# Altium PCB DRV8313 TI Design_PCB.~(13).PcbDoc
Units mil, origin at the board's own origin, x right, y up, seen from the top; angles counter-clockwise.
Board outline 4950 x 3450 mil, 2 copper layers (Top Layer, Bottom Layer), stack 62 mil thick; 47 components, 32 nets, 131 pads, 12 vias.
Unrouted connection lines stored in the file: 48.
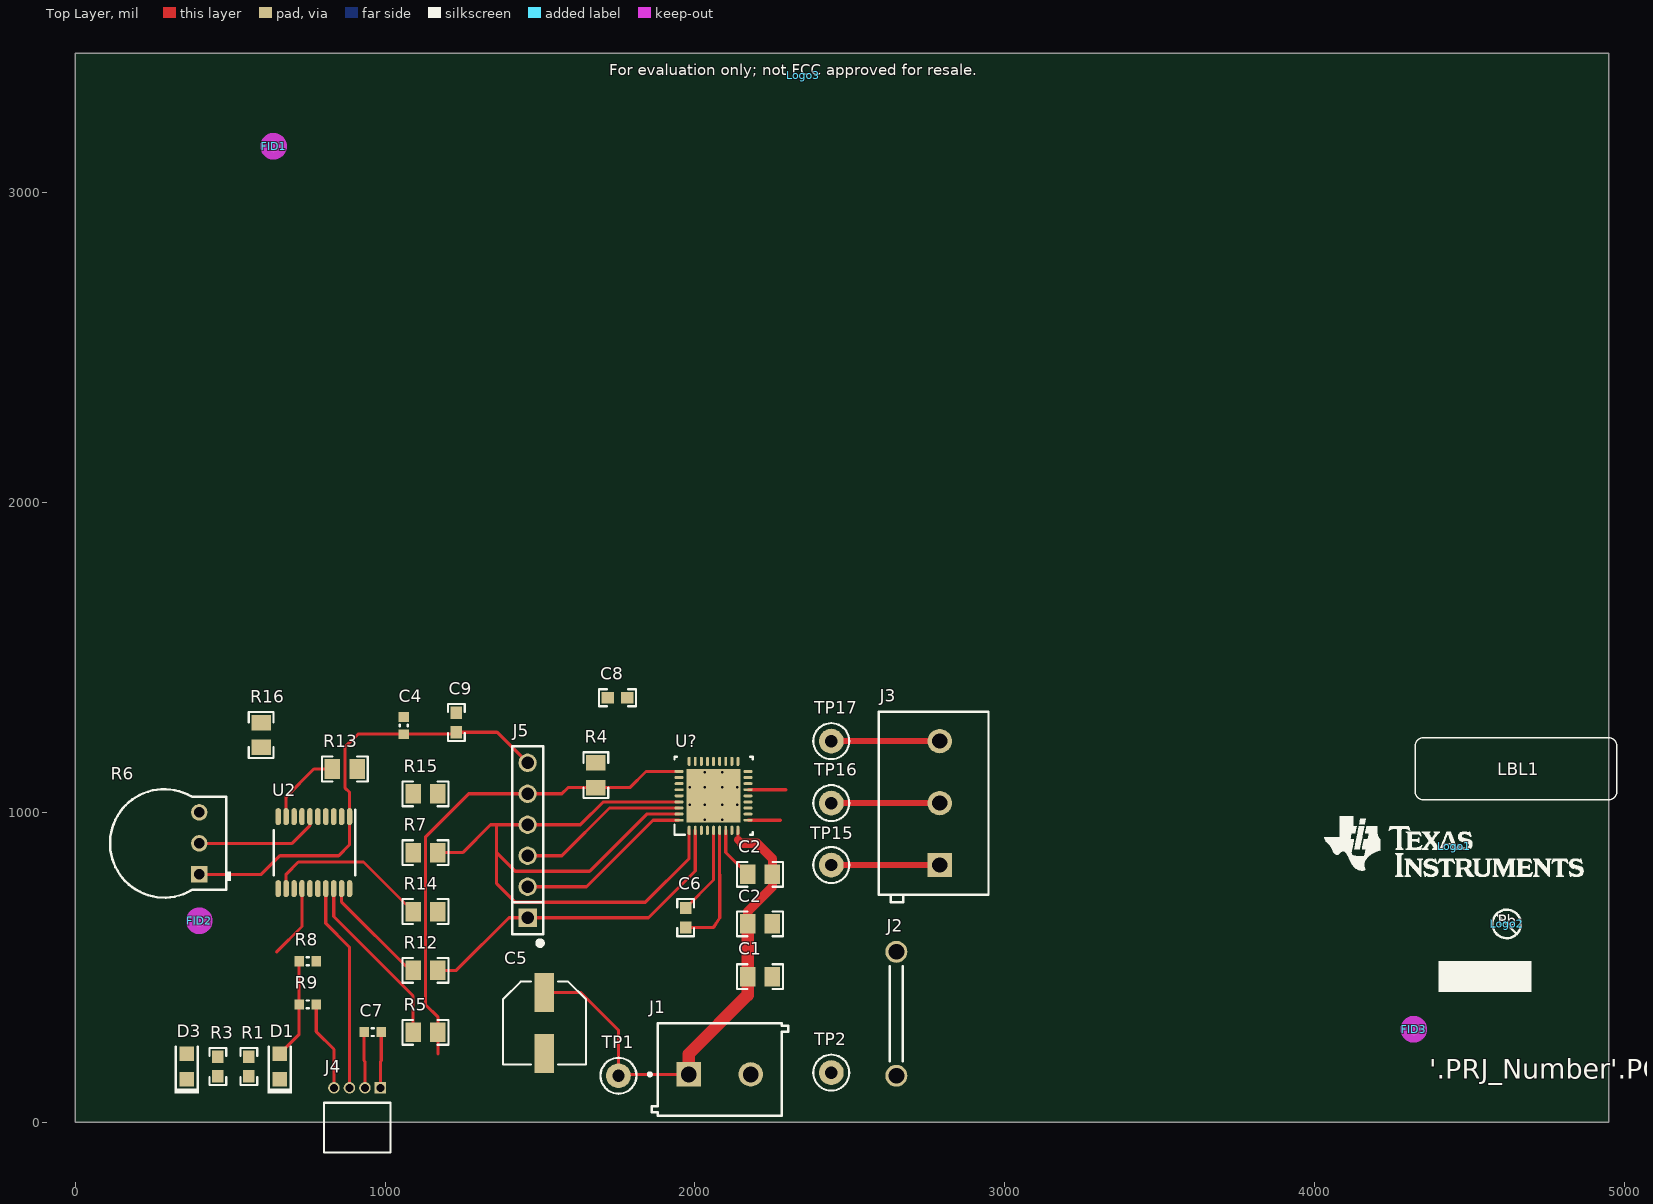
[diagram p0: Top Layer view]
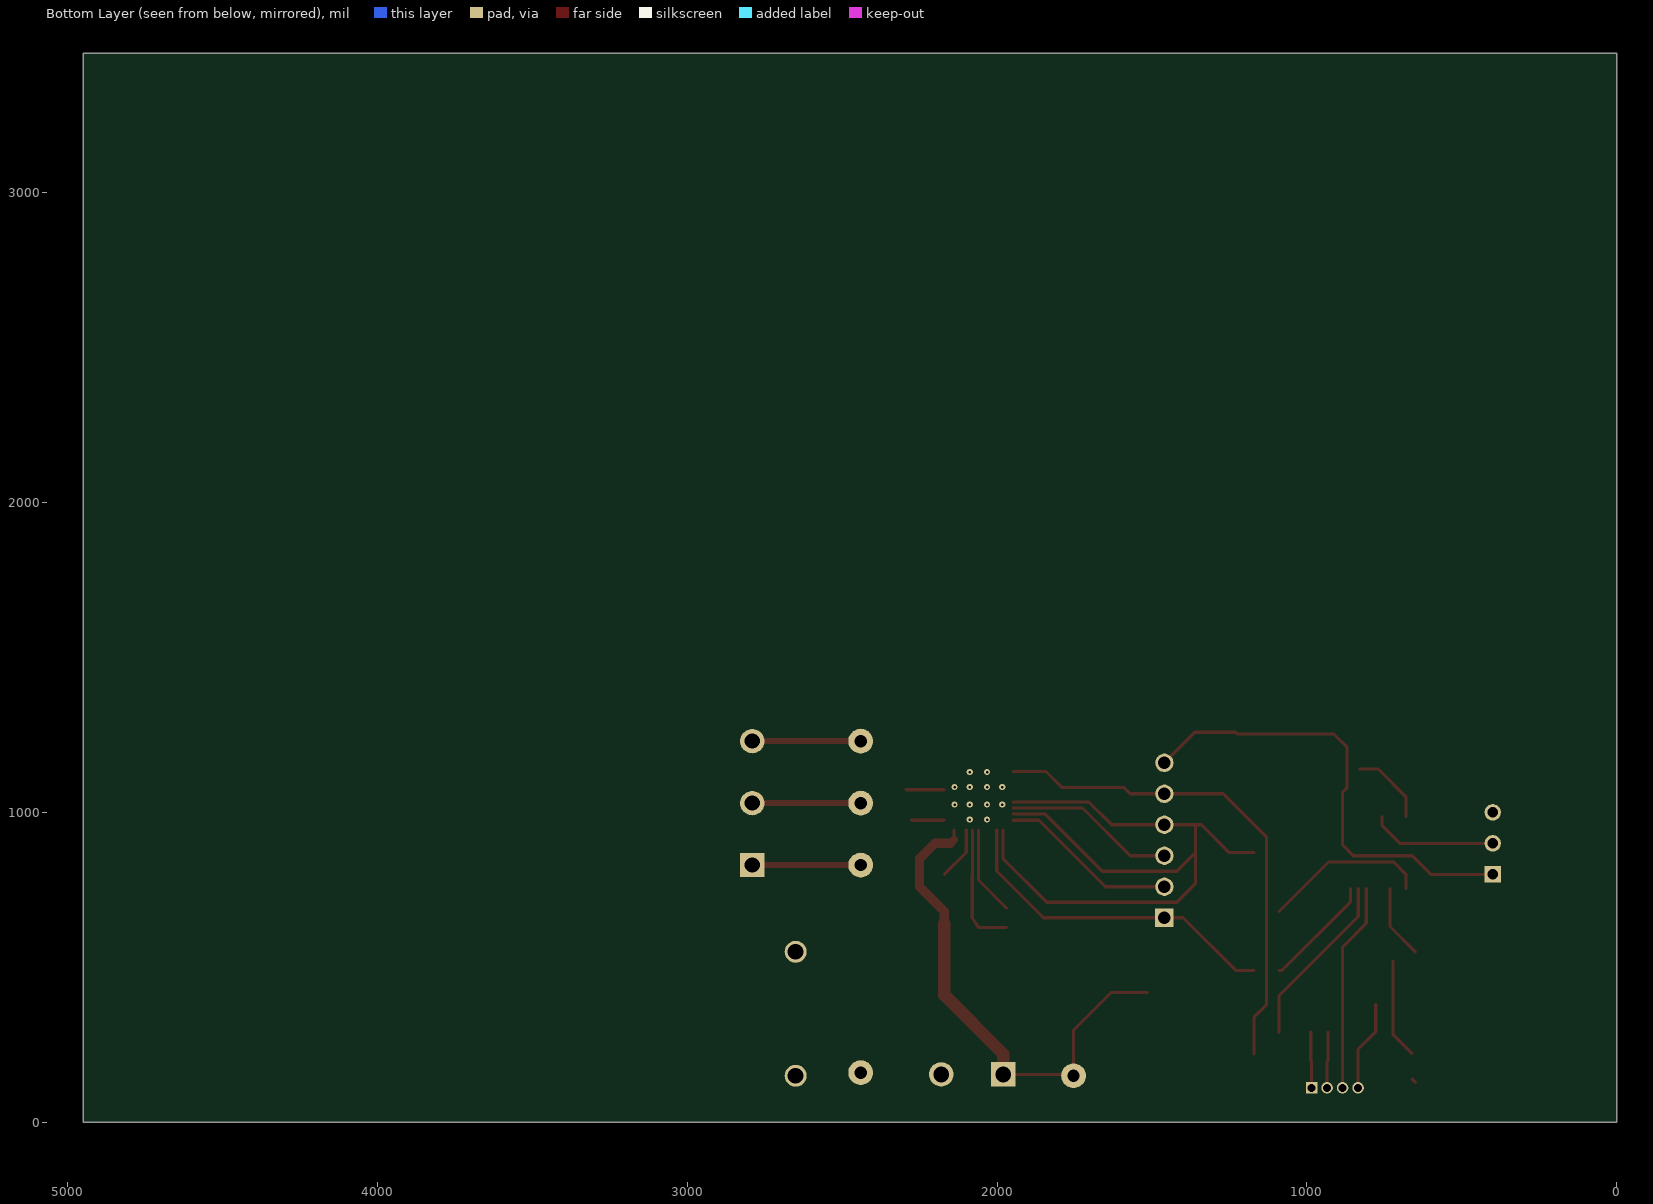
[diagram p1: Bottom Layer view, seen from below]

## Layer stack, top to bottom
Top Solder: solder mask 0.4, Solder Resist, Dk 3.5
Top Layer: signal copper 1.4
Dielectric1: core 59.2, FR-4, Dk 4.8
Bottom Layer: signal copper 1.4
Bottom Solder: solder mask 0.4, Solder Resist, Dk 3.5

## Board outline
0,0 4950,0 4950,3450 0,3450

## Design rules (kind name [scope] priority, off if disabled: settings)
AcuteAngle [All] p1: minimum=4.50000000000000E+0001 checktracksonly=FALSE
AssemblyTestPointUsage [All] p1: valid=2
BoardOutlineClearance BoardOutlineClearance_MountingHoles [OnCopper and InComponentClass('Mounting Holes')] p1: gap=40
BoardOutlineClearance BoardOutlineClearance_Poly [OnCopper and IsPoly] p2: gap=25
BoardOutlineClearance [OnCopper and Not InComponentClass('Logo') and not InComponentClass('FiducialMark') and not InRegion(1000,500,4000,800) and not InPoly] p3: gap=75
Clearance Clearance_Keepouts [((IsTrack Or IsArc) And Not InPoly) And IsFree and IsKeepOut vs ((IsTrack Or IsArc) And Not InPoly) And IsFree and IsKeepOut] p1: gap=0
Clearance Clearance_Poly [InPolygon] p2: gap=25
Clearance [All] p3: gap=7.87
ComponentClearance ComponentClearance_MountingHoles_FiducialMarks [InComponentClass('Mounting Holes') vs InComponentClass('FiducialMark')] p1: gap=50 collisioncheckmode=3 verticalgap=10 showdistances=FALSE
ComponentClearance ComponentClearance_Shunt [InComponentClass('Header') vs InComponentClass('Shunt')] p2: gap=0 collisioncheckmode=3 verticalgap=0 showdistances=FALSE
ComponentClearance ComponentClearance_Logo [InComponentClass('Logo')] p3: gap=50 collisioncheckmode=3 verticalgap=10 showdistances=FALSE
ComponentClearance ComponentClearance_ScrewToNut [(HasFootprint('NY PMS 440 0025 PH')) vs (HasFootprint('Keystone_1902C'))] p4: gap=5 collisioncheckmode=3 verticalgap=10 showdistances=FALSE
ComponentClearance ComponentClearance_MountingHoles [InComponentClass('Mounting Holes')] p5: gap=250 collisioncheckmode=3 verticalgap=100000 showdistances=FALSE
ComponentClearance ComponentClearance_SmallPassives [HasFootprint('0201*') or HasFootprint('0402*') or HasFootprint('0508') or HasFootprint('0603*') or HasFootprint('0612') or HasFootprint('0805*') or HasFootprint('0815*') or HasFootprint('0830*') or HasFootprint('1206*') or HasFootprint('1210*') or HasFootprint('1808*') or HasFootprint('1812*') or HasFootprint('1825*') or HasFootprint('2010*') or HasFootprint('2220*') or HasFootprint('2225*') or HasFootprint('2512*') or HasFootprint('2728*') or HasFootprint('3518*') vs HasFootprint('0201*') or HasFootprint('0402*') or HasFootprint('0508') or HasFootprint('0603*') or HasFootprint('0612') or HasFootprint('0805*') or HasFootprint('0815*') or HasFootprint('0830*') or HasFootprint('1206*') or HasFootprint('1210*') or HasFootprint('1808*') or HasFootprint('1812*') or HasFootprint('1825*') or HasFootprint('2010*') or HasFootprint('2220*') or HasFootprint('2225*') or HasFootprint('2512*') or HasFootprint('2728*') or HasFootprint('3518*')] p6: gap=14.96 collisioncheckmode=3 verticalgap=10 showdistances=FALSE
ComponentClearance ComponentClearance_THtoSMT [IsThruComponent vs IsSMTComponent] p7: gap=40 collisioncheckmode=3 verticalgap=30 showdistances=FALSE
ComponentClearance ComponentClearance_THtoTH [IsThruComponent vs IsThruComponent] p8: gap=30 collisioncheckmode=3 verticalgap=30 showdistances=FALSE
ComponentClearance [All] p9: gap=30 collisioncheckmode=3 verticalgap=10 showdistances=FALSE
DiffPairsRouting [All] p1: maxlimit=100 minlimit=10 mostfreqgap=10 toplayer_minwidth=15 toplayer_maxwidth=15 toplayer_prefwidth=15 bottomlayer_minwidth=15 bottomlayer_maxwidth=15 bottomlayer_prefwidth=15 maxuncoupledlength=1000
FabricationTestPointUsage TestPointUsage [All] p1: valid=2 allowmultiple=FALSE
FabricationTestpoint Testpoint [All] p1: side=3 testpointundercomponent=TRUE minsize=40 maxsize=100 preferedsize=60 minholesize=0 maxholesize=40 preferedholesize=32 testpointgrid=1 allowsidetop=TRUE allowsidebottom=TRUE usegrid=TRUE gridtolerance=0.01
FanoutControl Fanout_LCC [IsLCC] p1: bgadir=Out bgaviamode=Centered fanoutstyle=Auto fanoutdirection=Alternating viagrid=1 // Fanout_LCC (Default Rule)
FanoutControl Fanout_BGA [IsBGA] p2: bgadir=Out bgaviamode=Centered fanoutstyle=Auto fanoutdirection=Alternating viagrid=1 // Fanout_BGA (Default Rule)
FanoutControl Fanout_Default [All] p4: bgadir=Out bgaviamode=Centered fanoutstyle=Auto fanoutdirection=Alternating viagrid=1 // Fanout_Default (Default Rule)
FanoutControl Fanout_Small [(CompPinCount < 5)] p5: bgadir=Out bgaviamode=Centered fanoutstyle=Auto fanoutdirection=OutThenIn viagrid=1 // Fanout_Small (Default Rule)
HoleSize [All] p1: absolutevalues=TRUE maxlimit=251 minlimit=7.87 maxpercent=80.000 minpercent=20.000
MinimumAnnularRing MinimumAnnularRing_ThermalPadVias [IsVia and InAnyComponent] p1: minimumring=5.91
MinimumAnnularRing [All] p2: minimumring=8
MinimumSolderMaskSliver MinimumSolderMaskSliver_Logo [InComponentClass('Logo') vs InComponentClass('Logo')] p1: minsoldermaskwidth=0.7
MinimumSolderMaskSliver [All] p2: minsoldermaskwidth=3.94
PlaneConnect [All] p1: planeconnectstyle=Relief reliefexpansion=10 reliefentries=4 reliefconductorwidth=10 reliefairgap=10
PolygonConnect [All] p1: connectstyle=Relief reliefconductorwidth=10 reliefentries=4 polygonreliefangle="90 Angle" airgapwidth=10
RoutingVias ThermalPadVias [IsVia and InAnyComponent] p1: holewidth=7.87 width=19.68 viastyle="Through Hole" minholewidth=7.87 minwidth=19.68 maxholewidth=12.99 maxwidth=23.62
RoutingVias [All] p2: holewidth=16 width=34 viastyle="Through Hole" minholewidth=7.87 minwidth=26 maxholewidth=40 maxwidth=65
SilkToBoardRegionClearance [Not ((IsComment or IsDesignator) And (Hide <> 'False')) and not InRegion(1000,500,4000,800)] p1:
SilkToSilkClearance SilkToSilkClearance_Pb-FreeLogo [(HasFootprint('Pb-Free_Overlay_Medium') OR HasFootprint('Pb-Free_Overlay_Small')) vs (HasFootprint('Pb-Free_Overlay_Medium') OR HasFootprint('Pb-Free_Overlay_Small'))] p1: silktosilkclearance=0
SilkToSilkClearance [All] p2: silktosilkclearance=4
SilkToSolderMaskClearance SilkToComponentPadClearance [IsPad and InAnycomponent] p1: minsilkscreentomaskgap=5 clearancetoexposedcopper=TRUE
SilkToSolderMaskClearance "Silk to Solder Mask Opening" [All] p2: minsilkscreentomaskgap=4 clearancetoexposedcopper=FALSE
SolderMaskExpansion [All] p1: expansion=1.97
Width [All] p1: maxlimit=100 minlimit=6 preferedwidth=10 checkconnectedcopper=TRUE
15 further rules are at their usual default settings.

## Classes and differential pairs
component class Logo: Logo1
component class FiducialMark: FID1 FID2 FID3
component class AssemblyNote: ZZ1 ZZ2 ZZ3 ZZ4
component class Label: LBL1
component class Header: J5

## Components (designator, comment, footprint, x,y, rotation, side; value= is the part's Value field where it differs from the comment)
C1 "C2012X5R2A104K125AA" 0805_HV 2210,470 r180 top
C2 "C2012X5R2A104K125AA" 0805_HV 2210,800 r0 top
C2 "C2012X5R2A104K125AA" 0805_HV 2210,640 r0 top
C4 "C0603C104K8RACTU" 0603L 1060,1280 r90 top
C5 "EEE-FK1K100XP" SM_RADIAL_D8 1514.19,320 r270 top
C6 "0.01uF" 0603 1970,660 r270 top
C7 "GRM188R71C102KA01D" 0603L 959.79,291 r0 top
C8 "GCM188R71C474KA55D" 0603 1750,1370 r0 top
C9 "GCM188R71C474KA55D" 0603 1230,1290 r90 top
D1 "LTST-C170KRKT" LED_LTST-C170_Red 660,180 r270 top
D3 "LTST-C170KGKT" LTST-C170KGKT_Green 360,180 r270 top
FID1 "Fiducial" Fiducial10-20 640,3150 r0 top
FID2 "Fiducial" Fiducial10-20 400,650 r0 top
FID3 "Fiducial" Fiducial10-20 4320,300 r0 top
J1 "OSTTC022162" On-Shore_OSTTC022162 2080,170 r0 top
J2 "D3082-05" Harwin_D3082-05 2650,350 r90 top
J3 "ED120/3DS" On-Shore_ED120_3DS 2790,1030 r90 top
J4 "851-43-004-20-001000" CONN_851-43-004-20-001000 909.79,111 r0 top
J5 "PEC06SAAN" Sullins_PEC06SAAN 1460,910 r90 top
LBL1 "Size: 0.65\" x 0.20 \"" Label_650x200 4650,1140.66 r0 top
Logo1 "Texas Instruments" TI_Stacked_Overlay_Small 4450,890 r0 top
Logo2 "Pb-Free Symbol" Pb-Free_Overlay_Small 4620,640 r0 top
Logo3 "FCC disclaimer" FCC_disclaimer 2350,3380 r0 top
R1 "CRCW0603330RJNEA" 0603 560,180 r90 top
R3 "CRCW0603330RJNEA" 0603 460,180 r90 top
R4 "CRCW080510K0JNEA" 0805_HV 1680,1120 r90 top
R5 "ERJ-6GEY0R00V" 0805_HV 1130,290 r0 top
R6 "3352T-1-503LF" Bourns_3352T 400,900 r90 top
R7 "ERJ-6GEY0R00V" 0805_HV 1130,870 r0 top
R8 "CRCW060347K0JNEA" 0603L 750,520 r180 top
R9 "CRCW06030000Z0EA" 0603L 750,380 r180 top
R12 "ERJ-6GEY0R00V" 0805_HV 1130,490 r0 top
R13 "ERJ-6GEY0R00V" 0805_HV 870,1140 r0 top
R14 "ERJ-6GEY0R00V" 0805_HV 1130,680 r0 top
R15 "ERJ-6GEY0R00V" 0805_HV 1130,1060 r0 top
R16 "ERJ-6GEY0R00V" 0805_HV 600,1250 r90 top
TP1 "5000" Keystone5000 1753.06,150 r0 top
TP2 "5001" Keystone5001 2440,160 r0 top
TP15 "5002" Keystone5002 2440,830 r0 top
TP16 "5002" Keystone5002 2440,1030 r0 top
TP17 "5002" Keystone5002 2440,1230 r0 top
U2 "MSP430G2553IPW20R" PW0020A_N 770,870 r270 top
U? "DRV8313RHHR" RHH0036C 2060,1053.43 r90 top
ZZ1 "This Assembly Note is for PCB labels only" AssemblyNoteLabel 355,7548 r0 top
ZZ2 "These assemblies are ESD sensitive, ESD precautions shall be observed." AssemblyNote 355,7439.11 r0 top
ZZ3 "These assemblies must be clean and free from flux and all contaminants. Use of no clean flux is not acceptable." AssemblyNote 355,7350.56 r0 top
ZZ4 "These assemblies must comply with workmanship standards IPC-A-610 Class 2, unless otherwise specified." AssemblyNote 355,7262 r0 top

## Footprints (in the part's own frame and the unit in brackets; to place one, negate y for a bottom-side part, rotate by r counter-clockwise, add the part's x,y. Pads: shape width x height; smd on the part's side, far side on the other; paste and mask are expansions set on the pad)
0603 [mm] "0603 from SM-752 data"
  rect 1x0.95 smd: 1(-0.8,0) 2(0.8,0)
  silkscreen extent -1.52,-0.69 1.52,0.69, body extent -0.87,-0.47 0.87,0.47, height 1
0603L [mm] "0603 from SM-752 data"
  rect 0.8x0.85 smd: 1(-0.7,0) 2(0.7,0)
  silkscreen extent -0.07,-0.33 0.07,0.33, body extent -0.87,-0.47 0.87,0.47, height 1
0805_HV [mil] "0805 with 30mil clearance between pads"
  rect 50x63 smd: 1(-40,0) 2(40,0)
  silkscreen extent -74,-40 74,40, body extent -43,-29 43,29, height 57
AssemblyNote [mil] "Assembly Note"
AssemblyNoteLabel [mil] "Assembly Note for PCB Labels"
Bourns_3352T [mm] "TH, 3-Leads, Body 9.53x8.89mm, Pitch 2.54mm"
  rect 1.35x1.35 hole 0.85: 1(-2.54,0)
  round 1.35 hole 0.85: 2(0,0) 3(2.54,0)
  silkscreen extent -4.44,-2.6 4.44,7.31, body extent -4.44,-2.21 4.45,7.32, height 3.81
CONN_851-43-004-20-001000 [mm] "MILL-MAX"
  rect 0.95x0.95 hole 0.65: 1(1.905,0)
  round 0.95 hole 0.65: 2(0.635,0) 3(-0.635,0) 4(-1.905,0)
  silkscreen extent -2.73,-5.31 2.73,-1.22, body extent -2.73,-5.31 2.73,0.23, height 2.23
FCC_disclaimer [mil]
Fiducial10-20 [mm]
  round 1 smd mask+0.5: 1(0,0)
  Top Layer keep-out circle w1.178: c0,0 r0.5
Harwin_D3082-05 [mm] "Shorting Plug, 10.16mm spacing, TH"
  round 1.8 hole 1.3: 1(-5.08,0) 2(5.08,0)
  silkscreen extent -3.9,-0.53 3.9,0.53, body extent -5.6,-0.52 5.61,0.52, height 6.63
Keystone5000 [mil] "For Keystone 500x miniature loop terminals"
  round 80 hole 40: 1(0,0)
  silkscreen extent -58,-58 58,58, body extent -49,-49 49,49, height 182
Keystone5001 [mil] "For Keystone 500x miniature loop terminals"
  round 80 hole 40: 1(0,0)
  silkscreen extent -58,-58 58,58, body extent -49,-49 49,49, height 182
Keystone5002 [mil] "For Keystone 500x miniature loop terminals"
  round 80 hole 40: 1(0,0)
  silkscreen extent -58,-58 58,58, body extent -49,-49 49,49, height 182
Label_650x200 [mil] "Thermal Transfer Label"
  silkscreen extent -325,-100 325,100, body extent -325,-100 325,100, height 1
LED_LTST-C170_Red [mm] "LITE-ON"
  rect 1.2x1.2 smd: 1(-1.05,0) 2(1.05,0)
  silkscreen extent -1.6,-1 2.2,1, body extent -1.05,-0.67 1.05,0.67, height 1.1
LTST-C170KGKT_Green [mm] "LITE-ON"
  rect 1.2x1.2 smd: 1(-1.05,0) 2(1.05,0)
  silkscreen extent -1.6,-1 2.2,1, body extent -1.05,-0.67 1.05,0.67, height 1.1
On-Shore_ED120_3DS [mm] "ONSHORE"
  rrect5% 2x2 hole 1.25: 1(-5.08,0)
  round 2 hole 1.25: 2(0,0) 3(5.08,0)
  silkscreen extent -8.14,-4 7.5,5, body extent -8.32,-4 7.62,5, height 13
On-Shore_OSTTC022162 [mm] "THD, 2-Leads, Body 10.16x7.6mm, Pitch 5.08mm"
  rect 2x2 hole 1.3: 1(-2.54,-0.4)
  round 2 hole 1.3: 2(2.54,-0.4)
  silkscreen extent -5.85,-3.8 5.6,3.8, body extent -5.58,-3.8 5.6,3.8, height 10.31
Pb-Free_Overlay_Small [mil]
  silkscreen extent -46,-46 46,46
PW0020A_N [mm] "TSOP, 20-Leads, Body 6.5x4.4mm, Pitch 0.65mm, IPC Medium Density"
  oval 1.4x0.45 smd: 1(-2.95,2.925) 2(-2.95,2.275) 3(-2.95,1.625) 4(-2.95,0.975) 5(-2.95,0.325) 6(-2.95,-0.325) 7(-2.95,-0.975) 8(-2.95,-1.625) 9(-2.95,-2.275) 10(-2.95,-2.925) 11(2.95,-2.925) 12(2.95,-2.275) 13(2.95,-1.625) 14(2.95,-0.975) 15(2.95,-0.325) 16(2.95,0.325) 17(2.95,0.975) 18(2.95,1.625) 19(2.95,2.275) 20(2.95,2.925)
  silkscreen extent -3.5,-3.3 1.85,3.4, body extent -3.21,-3.25 3.21,3.25, height 1
RHH0036C [mm] "QFN, 36-Leads, Body 6x6mm, Pitch 0.5mm, Thermal Pad 4.4x4.4mm, TI Recommended"
  oval 0.75x0.24 smd: 1(-2.825,2) 2(-2.825,1.5) 3(-2.825,1) 4(-2.825,0.5) 5(-2.825,0) 6(-2.825,-0.5) 7(-2.825,-1) 8(-2.825,-1.5) 9(-2.825,-2) 19(2.825,-2) 20(2.825,-1.5) 21(2.825,-1) 22(2.825,-0.5) 23(2.825,0) 24(2.825,0.5) 25(2.825,1) 26(2.825,1.5) 27(2.825,2)
  oval 0.24x0.75 smd: 10(-2,-2.825) 11(-1.5,-2.825) 12(-1,-2.825) 13(-0.5,-2.825) 14(0,-2.825) 15(0.5,-2.825) 16(1,-2.825) 17(1.5,-2.825) 18(2,-2.825) 28(2,2.825) 29(1.5,2.825) 30(1,2.825) 31(0.5,2.825) 32(0,2.825) 33(-0.5,2.825) 34(-1,2.825) 35(-1.5,2.825) 36(-2,2.825)
  rect 4.4x4.4 smd paste-2.2: 37(0,0)
  silkscreen extent -3.2,-3.2 3.2,3.2, body extent -3.05,-3.05 3.05,3.05, height 1.01
SM_RADIAL_D8 [mm] "6.3 x 7.7mm:  Panasonic D8"
  rect 3.2x1.6 smd: 1(-2.5,0) 2(2.5,0)
  silkscreen extent -3.4,-3.4 3.4,3.4, body extent -3.4,-3.4 3.4,3.4, height 8.01
Sullins_PEC06SAAN [mm] "TH, 6-Leads, Body 608x100mil, Pitch 100mil"
  rect 1.5x1.5 hole 1.016: 1(-6.35,0)
  round 1.5 hole 1.016: 2(-3.81,0) 3(-1.27,0) 4(1.27,0) 5(3.81,0) 6(6.35,0)
  silkscreen extent -8.64,-1.27 7.72,1.27, body extent -7.72,-1.27 7.72,1.27, height 8.59
TI_Stacked_Overlay_Small [mil]
  silkscreen extent -418,-98 418,98

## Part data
C1 C2 C2: "CAP, CERM, 0.1 µF, 100 V, +/- 10%, X5R, 0805"
C4: "CAP, CERM, 0.1 µF, 10 V, +/- 10%, X7R, 0603"
C5: "CAP, AL, 10 µF, 80 V, +/- 20%, 2.4 ohm, AEC-Q200 Grade 2, SMD"
C6: library part Cap, "Capacitor"
C7: "CAP, CERM, 1000 pF, 16 V, +/- 10%, X7R, 0603"
C8 C9: "CAP, CERM, 0.47 µF, 16 V, +/- 10%, X7R, AEC-Q200 Grade 1, 0603"
D1: "LED, Red, SMD"
D3: "LED, Green, SMD"
FID1 FID2 FID3: "Fiducial mark.  There is nothing to buy or mount."
J1: "Terminal Block, 2-pole, 200mil, TH"
J2: "1mm Uninsulated Shorting Plug, 10.16mm spacing, TH"
J3: "Terminal Block, 5.08 mm, 3x1, Brass, TH"
J4: "SOCKET .050\" GRID SIP 4 POS R/A, TH"
J5: "Header, 100mil, 6x1, Tin, TH"
LBL1: library part THT-14-423-10, "Thermal Transfer Printable Labels, 0.650\" W x 0.200\" H - 10,000 per roll"
Logo1: library part TI_Logo, "Texas Instrument Corporate Signature"
Logo2: library part Pb-Free
Logo3: library part FCC_disclaimer, "FCC_disclaimer"
R1 R3: "RES, 330, 5%, 0.1 W, 0603"
R4: "RES, 10 k, 5%, 0.125 W, 0805"
R5 R7 R12 R13 R14 R15 R16: "RES, 0, 5%, 0.125 W, 0805"
R6: "Trimming Potentiometer, 50K, 0.5W, TH"
R8: "RES, 47 k, 5%, 0.1 W, 0603"
R9: "RES, 0, 5%, 0.1 W, 0603"
TP1: "Test Point, Miniature, Red, TH"
TP2: "Test Point, Miniature, Black, TH"
TP15 TP16 TP17: "Test Point, Miniature, White, TH"
U2: "16 MHz Mixed Signal Microcontroller with 16 KB Flash, 512 B SRAM and 24 GPIOs, -40 to 85 degC, 20-pin SOP (PW), Green (RoHS & no Sb/Br)"
U?: "2.5-A Triple 1/2-H Bridge Driver, RHH0036C"
ZZ1: library part AssemblyNoteLabel
ZZ2 ZZ3 ZZ4: library part AssemblyNote

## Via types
v1: diameter 19.68, hole 7.87, Top Layer to Bottom Layer, 12 vias

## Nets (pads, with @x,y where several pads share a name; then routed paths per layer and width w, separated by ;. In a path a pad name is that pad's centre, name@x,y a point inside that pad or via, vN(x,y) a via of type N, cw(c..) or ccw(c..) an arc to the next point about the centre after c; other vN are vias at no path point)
COMPN: C1.1 C2.2@2250,640 C4.2 C5.2 C7.2 C8.2 C9.2 J1.2 J2.1 J2.2 J4.1 R3.2 R6.3 TP2.1 U2.20 U?.11 U?.12 U?.16 U?.21 U?.22 U?.29 U?.37 | length 181.1
  Top Layer w10: J4.1 984.79,196 987.35,198.55 C7.2
  other v1: 2031.85,976.66 2088.15,976.66 1983.23,1025.28 2031.85,1025.28 2088.15,1025.28 2136.77,1025.28 1983.23,1081.58 2031.85,1081.58 2088.15,1081.58 2136.77,1081.58 2031.85,1130.2 2088.15,1130.2
CPH: C6.2 U?.6 | length 409.5
  Top Layer w10: C6.2 2060,628.5 2080,660 U?.6
CPL: C6.1 U?.5 | length 288
  Top Layer w10: C6.1 2060,781.5 U?.5
EN: J5.4 R7.2 U?.1 U?.33 U?.35 | length 2522.2
  Top Layer w10: R7.2 1250,870 1340,960 1360,960 ; U?.35 1844.38,994.38 1660,810 1420,810 1360,870 ; U?.33 1703.75,1033.75 1630,960 J5.4 1360,960 ; U?.1 1981.26,851.26 1840,710 1420,710 1360,770 1360,870 ; 1360,870 1360,960
IN1: J5.1 R12.2 U?.2 | length 1095.2
  Top Layer w10: R12.2 1230,490 1400,660 J5.1 1850,660 2000.94,810.94 U?.2
IN2: J5.2 R13.2 U?.36 | length 577.7
  Top Layer w10: J5.2 1650,760 1864.69,974.69 U?.36
IN3: J5.3 R14.2 U?.34 | length 552.6
  Top Layer w10: J5.3 1570,860 1724.06,1014.06 U?.34
NetD1_2: D1.2 R1.1 | length 14.4
  Top Layer w10: D1.2@649.84,128.5 D1.2
NetD3_2: D3.2 R3.1
NetJ4_4: J4.4 R9.1 | length 292.7
  Top Layer w10: R9.1 777.56,292.44 834.79,235.21 J4.4
NetR5_1: R5.1 U2.18 | length 569.9
  Top Layer w10: U2.18 833.98,663.78 1090,407.75 R5.1
NetR7_1: R7.1 U2.8
NetR15_1: R15.1 U2.11
NetR16_1: R16.1 U2.10
NetU?_3: U?.3 U?.17 U?.20 U?.23 U?.24 U?.30 U?.31 U?.32
NFAULT: J5.5 R1.2 R4.1 R5.2 U?.28 | length 1623.2
  Top Layer w10: 1170,220 R5.2 1170,340 1130,380 1130,920 1270,1060 J5.5 1570,1060 1590,1080 R4.1 1790,1080 1842.17,1132.17 U?.28
NRESET: R16.2 U?.26
NSLEEP: R15.2 U?.27
OUT1: J3.1 TP15.1 U?.10 | length 454.1
  Top Layer w10: U?.10 2275.31,974.69
  Top Layer w20: TP15.1 J3.1
OUT2: J3.2 TP16.1 U?.13 | length 350
  Top Layer w20: TP16.1 J3.2
OUT3: J3.3 TP17.1 U?.15 | length 471.9
  Top Layer w10: U?.15 2293.12,1073.12
  Top Layer w20: TP17.1 J3.3
POT: R6.2 U2.6 | length 409.8
  Top Layer w10: R6.2 700,900 757.2,957.2 U2.6
PUSH: U2.7
PWMA: R12.1 U2.19 | length 365.2
  Top Layer w10: U2.19 859.57,710.43 1080,490 R12.1
PWMB: R13.1 U2.9 | length 251
  Top Layer w10: U2.9 680.43,1050.43 770,1140 R13.1
PWMC: R14.1 U2.12 | length 538.8
  Top Layer w10: U2.12 680.43,800.43 720,840 930,840 R14.1
RESET: C7.1 J4.2 R8.1 U2.16 | length 181.1
  Top Layer w10: C7.1 932.23,198.55 934.79,196 J4.2
STATUS: D3.1 U2.14 | length 237.7
  Top Layer w10: 650,550 731.61,631.61 U2.14
TEST: J4.3 U2.17 | length 674.5
  Top Layer w10: U2.17 808.39,641.61 884.79,565.21 J4.3
V3P3: C4.1 C8.1 C9.1 D1.1 J5.6 R4.2 R6.1 R8.2 R9.2 U2.1 U?.25 | length 1821.1
  Top Layer w10: R6.1 600,800 660,860 850,860 885.16,895.16 U2.1 885.16,1064.84 870,1080 870,1210 912.44,1252.44 C4.1 1223.94,1252.44 C9.1 1361.5,1258.5 J5.6 ; D1.1 722.44,283.78 R9.2 R8.2
VCP: C2.1@2170,800 U?.7 | length 171.5
  Top Layer w10: U?.7 2099.37,870.63 C2.1@2170,800
VM: C1.2 C2.1@2170,640 C2.2@2250,800 C5.1 J1.1 TP1.1 U?.9 U?.19 | length 1644
  Top Layer w10: C5.1 1631.57,418.43 1753.06,296.94 TP1.1 ; TP1.1@1757.31,154.25 J1.1 ; 2138.74,911.26 U?.9
  Top Layer w25: 2138.74,911.26 2150,900
  Top Layer w30: 2150,900 2200,900 2250,850 C2.2@2250,800 ; C2.1@2170,640 2170,680 2250,760 C2.2@2250,810
  Top Layer w40: J1.1 1980,220 2170,410 C1.2 C2.1@2170,640
pads on no net: FID1.1 FID2.1 FID3.1 U2.2 U2.3 U2.4 U2.5 U2.13 U2.15 U?.4 U?.8 U?.14 U?.18

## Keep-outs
Keep-Out Layer:
  text ".Layer_Name" at 577,-858.49 h60

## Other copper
Top Layer:
  text ".Layer_Name" at 577,-858.49 h60
Bottom Layer:
  text ".Layer_Name" at 577,-858.49 h60

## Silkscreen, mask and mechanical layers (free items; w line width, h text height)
Top Overlay:
  region: 4700,520 4400,520 4400,420 4700,420
  text "This document can handle board shapes up to 7.9in x 10in, although" at 0,6345 h60
  text "our panel vendors top out at 7in x 10in." at 0,6220.94 h60
  text "To re-size the board shape, do the following:" at 55,6096.88 h60
  text "Select lines on M1 Board Outline and delete (easy in single layer mode...shift+s)" at 115,5972.82 h60
  text "Draw a rectangle using lines (example will be for a 4\" x 6\" board" at 115,5848.76 h60
  text "Enter Place Line mode (keyboard pl)" at 325,5724.71 h60
  text "keyboard jo to jump to origin, hit enter" at 325,5600.65 h60
  text "keyboard jl to jump to location, set x to 6000, hit enter twice" at 325,5476.59 h60
  text "keyboard jl to jump to location, set x to 6000 and y to 4000, hit enter twice" at 325,5352.53 h60
  text "keyboard jl to jump to location, set x to 0 and y to 4000, hit enter twice" at 325,5228.47 h60
  text "keyboard jo to jump to origin, hit enter" at 325,5104.41 h60
  text "Hit ESC twice to exit place line mode" at 325,4980.35 h60
  text "Select lines on M1 Board Outline" at 115,4836.3 h60
  text "Menu Design|Board Shape|Define from Selected Objects (keyboard dsd)" at 115,4732.24 h60
  text "If you re-size the board, don't forget to move the drill table strings on the" at 0,4413 h60
  text "Drill Drawing Layer...they should be just to the right of your board shape" at 193,4307 h60
  text "'.PRJ_Number'.PCB_Rev-" at 4370,120 h108.27
  text ".Layer_Name" at 577,-858.49 h60
Bottom Overlay:
  text ".Layer_Name" at 577,-858.49 h60
Top Paste:
  text ".Layer_Name" at 577,-858.49 h60
Bottom Paste:
  text ".Layer_Name" at 577,-858.49 h60
Top Solder:
  text ".Layer_Name" at 577,-858.49 h60
  text ".Layer_Name" at 577,-858.49 h60
Bottom Solder:
  text ".Layer_Name" at 577,-858.49 h60
Drill Guide:
  text ".Layer_Name" at 577,-858.49 h60
M1 Board Outline:
  the board outline again, w10
  text ".Layer_Name" at 577,-858.49 h60
M2 Board Dimensions:
  rectangle: 0,-275 125,-150
  rectangle: 125,-400 500,-275
  lines w7: 0,-275 1000,-275 ; 125,-400 125,-150 ; 250,-400 250,-150 ; 500,-400 500,-150 ; 750,-400 750,-150 ; 0,-400 1000,-400 1000,-150 0,-150 0,-400
  text ".Layer_Name" at 577,-858.49 h60
M3 3D STEP Top:
  text ".Layer_Name" at 577,-858.49 h60
M4 3D STEP Bottom:
  text ".Layer_Name" at 577,-858.49 h60
M5 Assembly Top:
  lines w10: -292,-930.17 6308,-930.17 ; -292,-726.83 6310,-726.83 ; -292,-523.5 -292,-1133.5 3713,-1133.5 6310,-1133.5 6310,-523.5 -291.5,-523.5 -291.5,-1133.5 1284,-1133.5 ; 2173,-1133.5 2173,-523.5 ; 3440,-726.83 3440,-523.5 ; 4280,-726.83 4280,-523.5 ; 4902,-1140 4902,-937.17
  text "COMPONENTS MARKED 'DNP' SHOULD NOT BE POPULATED." at 1153.5,-318.5 h60
  text "ASSEMBLY VARIANT:" at 1153,-434 h60
  text ".VariantName" at 2189,-434 h60
  text "PCB VIEWED FROM TOP SIDE" at -228.5,-655.67 h60
  text "BOARD #:" at 2248,-655.67 h60
  text ".PRJ_Number" at 2793.5,-655.67 h60
  text "REV:" at 3638,-655.67 h60
  text ".PCB_Rev" at 3929.5,-655.67 h60
  text "SVN REV:" at 4476,-655.67 h60
  text ".VersionControl_RevNumber" at 4982,-655.67 h60
  text "TID #:" at 2248,-859 h60
  text ".TID" at 2793.5,-859 h60
  text "PLOT NAME =" at -228.5,-1064.34 h60
  text ".plot_File_Name" at 577,-1064.34 h60
  text "GENERATED    :" at 2250,-1064.34 h60
  text ".Print_Date" at 3119.5,-1064.34 h60
  text ".Print_Time" at 3848.5,-1064.34 h60
  text "TEXAS INSTRUMENTS" at 5113,-1064.34 h60
M6 Assembly Bottom:
  lines w10: -292.5,-727.33 6309.5,-727.33 ; -290.5,-930.67 6309.5,-930.67 ; 1115.5,-1140.5 1115.5,-937.67 ; 1737.5,-727.33 1737.5,-524 ; 2577.5,-727.33 2577.5,-524 ; 3844.5,-1134 3844.5,-524 ; 4733.5,-1134 6309,-1134 6309,-524 -292.5,-524 -292.5,-1134 2304.5,-1134 6309.5,-1134 6309.5,-524
  text "COMPONENTS MARKED 'DNP' SHOULD NOT BE POPULATED." at 6102,-318 h60
  text ".VariantName" at 5058,-434 h60
  text "ASSEMBLY VARIANT:" at 6097,-434 h60
  text ".VersionControl_RevNumber" at 1035.5,-656.17 h60
  text "SVN REV:" at 1541.5,-656.17 h60
  text ".PCB_Rev" at 2088,-656.17 h60
  text "REV:" at 2379.5,-656.17 h60
  text ".PRJ_Number" at 3224,-656.17 h60
  text "BOARD #:" at 3769.5,-656.17 h60
  text "PCB VIEWED FROM BOTTOM SIDE" at 6246,-656.17 h60
  text ".TID" at 3224,-859.5 h60
  text "TID #:" at 3769.5,-859.5 h60
  text "TEXAS INSTRUMENTS" at 904.5,-1064.84 h60
  text ".Print_Time" at 2169,-1064.84 h60
  text ".Print_Date" at 2898,-1064.84 h60
  text "GENERATED    :" at 3767.5,-1064.84 h60
  text ".plot_File_Name" at 5440.5,-1064.84 h60
  text "PLOT NAME =" at 6246,-1064.84 h60
M9 Title Sheet:
  drawing of 57 lines, arcs and shapes, not listed
  text "1" at 739.84,8036.5 h70
  text "2" at 3235.5,8036.5 h70
  text "3" at 5724.84,8036.5 h70
  text "4" at 8231.51,8036.5 h70
  text "5" at 10730.5,8036.5 h70
  text "6" at 13235.5,8036.5 h70
  text "A" at -416.5,6893.5 h70
  text "A" at 14383.5,6893.5 h70
  text "B" at -416.5,4513.5 h70
  text "B" at 14383.5,4513.5 h70
  text "C" at -416.5,2138.5 h70
  text "C" at 14383.5,2138.5 h70
  text "PROJECT TITLE:" at 11343.5,277.5 h45
  text ".PRJ_Title" at 11393.5,144.17 h70
  text "DESIGNED FOR:" at 11343.5,-23.5 h45
  text ".PRJ_Customer" at 11393.5,-163.5 h70
  text "D" at -416.5,-231.5 h70
  text "D" at 14383.5,-231.5 h70
  text "FILE NAME:" at 11343.5,-323.5 h45
  text ".PCB_File_Name_No_Path" at 11393.5,-443.5 h70
  text "Texas Instruments (TI) and/or its licensors do not warrant the accuracy or completeness of this specification" at 6374,-605.34 h45
  text "ENGINEER:" at 11343.5,-613.5 h45
  text "LAYOUT BY:" at 12848.5,-613.5 h45
  text "or any information contained therein. TI and/or its licensors do not warrant that this design will meet" at 6329.01,-718 h45
  text ".PRJ_Engineer" at 11393.5,-768.49 h70
  text ".PCB_Layout" at 12899,-768.49 h70
  text "the specifications, will be suitable for your application or fit for any particular purpose, or will operate in" at 6329.01,-830.67 h45
  text ".Layer_Name" at 577,-858.49 h60
  text "ALTIUM DESIGNER VERSION:" at 12848.5,-923.5 h45
  text "an implementation. TI and/or its licensors do not warrant that the design is production worthy. You should" at 6329.01,-943.33 h45
  text "completely validate and test your design implementation to confirm the system functionality for your application." at 6374,-1056 h45
  text ".print_Scale" at 11393.5,-1056.83 h70
  text ".Application_BuildNumber" at 12899,-1056.83 h70
  text "1" at 739.84,-1263.5 h70
  text "2" at 3235.5,-1263.5 h70
  text "3" at 5724.84,-1263.5 h70
  text "4" at 8231.51,-1263.5 h70
  text "5" at 10730.5,-1263.5 h70
  text "6" at 13235.5,-1263.5 h70
M10 Fab Notes:
  drawing of 173 lines, arcs and shapes, not listed
  text "DESIGN INFORMATION" at 12378.02,6201 h60
  text "MIN. TRACK WIDTH:" at 11733.46,6021 h60
  text "8" at 12829.7,6021 h60
  text "MIL" at 12984.46,6021 h60
  text "MIN. CLEARANCE:" at 11733.46,5889 h60
  text "0.2" at 12769.7,5889 h60
  text "mm" at 12984.46,5889 h60
  text "MIN. VIA PAD SIZE:" at 11733.46,5757 h60
  text "24" at 12799.71,5757 h60
  text "MIL" at 12984.46,5757 h60
  text "0.05mm (2MIL)" at 12428.46,5615.29 h60
  text "MINIMUM ANNULAR RING" at 11404.23,5611 h60
  text "EXTERNAL" at 13136.46,5611 h60
  text "PER" at 11604.23,5493 h60
  text "IPC-D-275 CLASS 2 LEVEL C" at 11824.23,5493 h60
  text "MIL, HOLES" at 13312.46,5380.71 h60
  text "+/-" at 12920,5380 h60
  text "+/-" at 13774,5380 h60
  text "REGISTRATION TOLERANCES:" at 11404.23,5375 h60
  text "METAL" at 12604,5375 h60
  text "5" at 13180.2,5375 h60
  text "3" at 14013.2,5375 h60
  text "MIL" at 14129.46,5375 h60
  text "+/-" at 13774,5262 h60
  text "HOLE SIZE TOLERANCE (UNLESS OTHERWISE SPECIFIED):" at 11404.23,5257 h60
  text "3" at 14013.2,5257 h60
  text "MIL" at 14129.46,5257 h60
  text "MATERIAL:" at 11329.46,5047.54 h60
  text "FR-4 High Tg" at 12315.9,4907.21 h60
  text "FR-408" at 11750.46,4898.64 h60
  text "OTHER" at 13238.46,4898.64 h60
  text "X" at 12161,4895 h60
  text "62 MIL (1.6mm) +/-10%" at 12070.56,4735.92 h60
  text "THICKNESS:" at 11404.23,4731.64 h60
  text "X" at 11942.4,4731.64 h60
  text "OTHER" at 13355.46,4731.64 h60
  text "TOLERANCE:" at 11404.23,4573.64 h60
  text "X" at 12243.53,4573.64 h60
  text "ANSI IPC-6012 TYPE 3 CLASS 2" at 12430.48,4573.64 h60
  text "OTHER +/-" at 12430.46,4417.64 h60
  text "BOW & TWIST:" at 11404.23,4260.64 h60
  text "X" at 12243.53,4260.64 h60
  text "ANSI IPC-6012 TYPE 3 CLASS 2" at 12430.48,4260.64 h60
  text "OTHER +/-" at 12430.46,4102.13 h60
  text "DRILLING:" at 11329.46,3963.64 h60
  text "REFERENCE:" at 11404.23,3846.64 h60
  text "X" at 12052.46,3846.64 h60
  text "AS SHOWN" at 12239.46,3846.64 h60
  text "X" at 12953.46,3846.64 h60
  text "NC_DRILL FILES" at 13090.46,3846.64 h60
  text "PTH COPPER THICKNESS:" at 11404.23,3688.64 h60
  text "X" at 12534.46,3688.64 h60
  text "20-30 um" at 12671.46,3688.64 h60
  text "OTHER" at 13388.46,3688.64 h60
  text "BOARD FINISH:" at 11329.46,3529.64 h60
  text "SILKSCREEN:" at 11484.68,3411.64 h60
  text "X" at 12433.46,3411.64 h60
  text "TOP" at 12559.46,3411.64 h60
  text "X" at 12943.46,3411.64 h60
  text "BOTTOM" at 13070.46,3411.64 h60
  text "SILKSCREEN COLOR:" at 11484.68,3244.64 h60
  text "X" at 12432.42,3244.64 h60
  text "WHITE" at 12559.46,3244.64 h60
  text "OTHER" at 13070.46,3244.64 h60
  text "X" at 12563.42,3085.44 h60
  text "GREEN" at 12690.46,3085.44 h60
  text "OTHER" at 13308.46,3085.44 h60
  text "SOLDER RESIST COLOR:" at 11484.68,3074.64 h60
  text "X" at 12563.42,2915.44 h60
  text "MATTE" at 12690.46,2915.44 h60
  text "SEMI-GLOSS" at 13308,2914.8 h60
  text "IMMERSION GOLD (ENIG)" at 12390.46,2726.92 h60
  text "ENEPIG" at 13728,2723.64 h60
  text "SURFACE FINISH:" at 11329.46,2722.64 h60
  text "X" at 12203.51,2722.64 h60
  text "IMM. TIN/SILVER OR EQUIV" at 11659,2565.64 h60
  text "OTHER" at 13090.46,2565.64 h60
  text "ARRAY/PANEL:" at 11329.46,2386.64 h60
  text "CUT AND TRIM PER M1 BOARD OUTLINE" at 12390.46,2382.35 h60
  text "N.C. ROUTE" at 12390.46,2230.64 h60
  text "X" at 13069.46,2230.64 h60
  text "V. SCORE" at 13256.46,2230.64 h60
  text "CERTIFICATION:" at 11329.46,2093.64 h60
  text "MATERIALS AND WORKMANSHIP FOR ALL PCBS" at 12054.46,2093.64 h60
  text "TO MEET OR EXCEED THE REQUIREMENTS OF:" at 12054.46,1995.64 h60
  text "X" at 11680.96,1859.13 h60
  text "ANSI IPC-A-600F CLASS ->" at 11819.96,1859.13 h60
  text "X" at 13459.02,1859.13 h60
  text "2" at 13577.96,1859.14 h60
  text "1" at 13262.96,1857.64 h60
  text "3" at 13931.96,1857.64 h60
  text "X" at 12495.02,1699.64 h60
  text "RoHS" at 12631.96,1699.64 h60
  text "OTHER" at 13276.36,1699.64 h60
  text "PER ORDER" at 13673.42,1699.64 h60
  text "ALL BOARDS MUST MEET OR EXCEED UL94-V0 REQUIREMENTS." at 11357,1534 h60
  text "PCB MUST BEAR THE UL94V-0 UL REGISTERED MATERIAL ID NUMBER" at 11357,1414 h60
  text "ADDITIONAL REQUIREMENTS:" at 11329.46,1240.64 h60
  text "MICROSECTION:" at 11404.23,1125.64 h60
  text "YES" at 12309.96,1125.64 h60
  text "REQUIRED" at 13171.46,969.49 h60
  text "BARE BOARD ELEC. TEST:" at 11404.23,966.64 h60
  text "NONE" at 12709.96,966.64 h60
  text "X" at 13044.46,966.64 h60
  text "PER ORDER" at 13763.46,966.64 h60
  text ".Layer_Name" at 577,-858.49 h60
M11 Gerber Information:
  lines w10: -292,-930.17 6308,-930.17 ; -292,-726.83 6310,-726.83 ; -292,-523.5 -292,-1133.5 3713,-1133.5 6310,-1133.5 6310,-523.5 -291.5,-523.5 -291.5,-1133.5 1284,-1133.5 ; 2173,-1133.5 2173,-523.5 ; 3440,-726.83 3440,-523.5 ; 4280,-726.83 4280,-523.5 ; 4902,-1140 4902,-937.17
  text "ALL ARTWORK VIEWED FROM TOP SIDE" at -228.5,-655.67 h60
  text "BOARD #:" at 2248,-655.67 h60
  text ".PRJ_Number" at 2793.5,-655.67 h60
  text "REV:" at 3638,-655.67 h60
  text ".PCB_Rev" at 3929.5,-655.67 h60
  text "SVN REV:" at 4476,-655.67 h60
  text ".VersionControl_RevNumber" at 4982,-655.67 h60
  text "LAYER NAME =" at -228.5,-858.49 h60
  text "TID #:" at 2248,-859 h60
  text ".TID" at 2793.5,-859 h60
  text "PLOT NAME =" at -228.5,-1064.34 h60
  text ".plot_File_Name" at 577,-1064.34 h60
  text "GENERATED    :" at 2250,-1064.34 h60
  text ".Print_Date" at 3119.5,-1064.34 h60
  text ".Print_Time" at 3848.5,-1064.34 h60
  text "TEXAS INSTRUMENTS" at 5113,-1064.34 h60
M12 Stackup:
  drawing of 191 lines, arcs and shapes, not listed
  text "Layer" at 9790.34,7830 h60
  text "Name" at 10200.26,7830 h60
  text "Material" at 11130,7830 h60
  text "Thickness" at 11989.77,7830 h60
  text "Constant" at 12639.6,7830 h60
  text "Board Layer Stack" at 13209.46,7830 h60
  text "1" at 9790.34,7710 h60
  text "Top Overlay" at 10200.26,7710 h60
  text "2" at 9790.34,7590 h60
  text "Top Solder" at 10200.26,7590 h60
  text "Solder Resist" at 11130,7590 h60
  text "0.40mil" at 11989.77,7590 h60
  text "3.5" at 12639.6,7590 h60
  text "3" at 9790.34,7470 h60
  text "Top Layer" at 10200.26,7470 h60
  text "Copper" at 11130,7470 h60
  text "1.40mil" at 11989.77,7470 h60
  text "4" at 9790.34,7350 h60
  text "Dielectric1" at 10200.26,7350 h60
  text "FR-4" at 11130,7350 h60
  text "59.20mil" at 11989.77,7350 h60
  text "4.8" at 12639.6,7350 h60
  text "5" at 9790.34,7230 h60
  text "Bottom Layer" at 10200.26,7230 h60
  text "Copper" at 11130,7230 h60
  text "1.40mil" at 11989.77,7230 h60
  text "6" at 9790.34,7110 h60
  text "Bottom Solder" at 10200.26,7110 h60
  text "Solder Resist" at 11130,7110 h60
  text "0.40mil" at 11989.77,7110 h60
  text "3.5" at 12639.6,7110 h60
  text "7" at 9790.34,6990 h60
  text "Bottom Overlay" at 10200.26,6990 h60
  text ".Layer_Name" at 577,-858.49 h60
M13 Component Bodies Top:
  text ".Layer_Name" at 577,-858.49 h60
M14 Component Bodies Bottom:
  text ".Layer_Name" at 577,-858.49 h60
M15 Courtyards Top:
  text ".Layer_Name" at 577,-858.49 h60
M16 Courtyards Bottom:
  text ".Layer_Name" at 577,-858.49 h60
Drill Drawing:
  lines w10: 5336.09,2630.87 5349.9,2630.87 5363.72,2617.06 5377.53,2630.87 5391.34,2630.87 5377.53,2644.68 5391.34,2658.5 5377.53,2658.5 5363.72,2672.31 5349.9,2658.5 5336.09,2658.5 5349.9,2644.68 5336.09,2630.87 ; 5336.09,2741.38 5336.09,2755.19 5349.9,2769 5336.09,2782.82 5336.09,2796.63 5349.9,2796.63 5363.72,2782.82 5377.53,2796.63 5391.34,2796.63 5391.34,2782.82 5377.53,2769 5391.34,2755.19 5391.34,2741.38 5377.53,2741.38 5363.72,2755.19 5349.9,2741.38 5336.09,2741.38 ; 5336.09,2920.95 5391.34,2920.95 5363.72,2865.7 5336.09,2920.95 ; 5336.09,3003.83 5349.9,3003.83 5349.9,2990.02 5377.53,2990.02 5377.53,3003.83 5391.34,3003.83 5391.34,3031.46 5377.53,3031.46 5377.53,3045.27 5349.9,3045.27 5349.9,3031.46 5336.09,3031.46 5336.09,3003.83 ; 5336.09,3114.34 5363.72,3128.15 5391.34,3114.34 5377.53,3141.96 5391.34,3169.59 5363.72,3155.78 5336.09,3169.59 5349.9,3141.96 5336.09,3114.34 ; 5336.09,3238.66 5391.34,3238.66 5391.34,3293.91 5336.09,3293.91 5336.09,3238.66
  lines w12: 5286,2579.76 8517.49,2579.76 ; 5286,3325.68 8517.49,3325.68 ; 5623.86,2455.44 5623.86,3450 ; 5955.86,2455.44 5955.86,3450 ; 6592.43,2455.44 6592.43,3450 ; 6851.57,2455.44 6851.57,3450 ; 7226.72,2455.44 7226.72,3450 ; 7951.05,2455.44 7951.05,3450 ; 5286,2455.44 8517.49,2455.44 8517.49,3450 5286,3450 5286,2455.44
  text "Symbol" at 5360.59,3362.98 h72
  text "Quantity" at 5661.16,3362.98 h72
  text "Finished Hole Size" at 5993.16,3362.98 h72
  text "Plated" at 6629.72,3362.98 h72
  text "Hole Type" at 6888.86,3362.98 h72
  text "Drill Layer Pair" at 7264.02,3362.98 h72
  text "Hole Tolerance" at 7988.35,3362.98 h72
  text "12" at 5661.16,3238.66 h60
  text "7.87mil (0.200mm)" at 5993.16,3238.66 h60
  text "PTH" at 6629.72,3238.66 h60
  text "Round" at 6888.86,3238.66 h60
  text "Top Layer - Bottom Layer" at 7264.02,3238.66 h60
  text "4" at 5661.16,3114.34 h60
  text "25.59mil (0.650mm)" at 5993.16,3114.34 h60
  text "PTH" at 6629.72,3114.34 h60
  text "Round" at 6888.86,3114.34 h60
  text "Top Layer - Bottom Layer" at 7264.02,3114.34 h60
  text "3" at 5661.16,2990.02 h60
  text "33.46mil (0.850mm)" at 5993.16,2990.02 h60
  text "PTH" at 6629.72,2990.02 h60
  text "Round" at 6888.86,2990.02 h60
  text "Top Layer - Bottom Layer" at 7264.02,2990.02 h60
  text "11" at 5661.16,2865.7 h60
  text "40.00mil (1.016mm)" at 5993.16,2865.7 h60
  text "PTH" at 6629.72,2865.7 h60
  text "Round" at 6888.86,2865.7 h60
  text "Top Layer - Bottom Layer" at 7264.02,2865.7 h60
  text "3" at 5661.16,2741.38 h60
  text "49.21mil (1.250mm)" at 5993.16,2741.38 h60
  text "PTH" at 6629.72,2741.38 h60
  text "Round" at 6888.86,2741.38 h60
  text "Top Layer - Bottom Layer" at 7264.02,2741.38 h60
  text "4" at 5661.16,2617.06 h60
  text "51.18mil (1.300mm)" at 5993.16,2617.06 h60
  text "PTH" at 6629.72,2617.06 h60
  text "Round" at 6888.86,2617.06 h60
  text "Top Layer - Bottom Layer" at 7264.02,2617.06 h60
  text "37 Total" at 5661.16,2492.74 h60
  text ".Layer_Name" at 577,-858.49 h60
M17 Embedded Cavity:
  text ".Layer_Name" at 577,-858.49 h60
M18 Embedded Assembly:
  text ".Layer_Name" at 577,-858.49 h60
M19 Embedded Keepout:
  text ".Layer_Name" at 577,-858.49 h60

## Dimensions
0,-400 to 1000,-400 on M2 Board Dimensions
0,0 to 0,3450 on M2 Board Dimensions
0,0 to 4950,0 on M2 Board Dimensions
